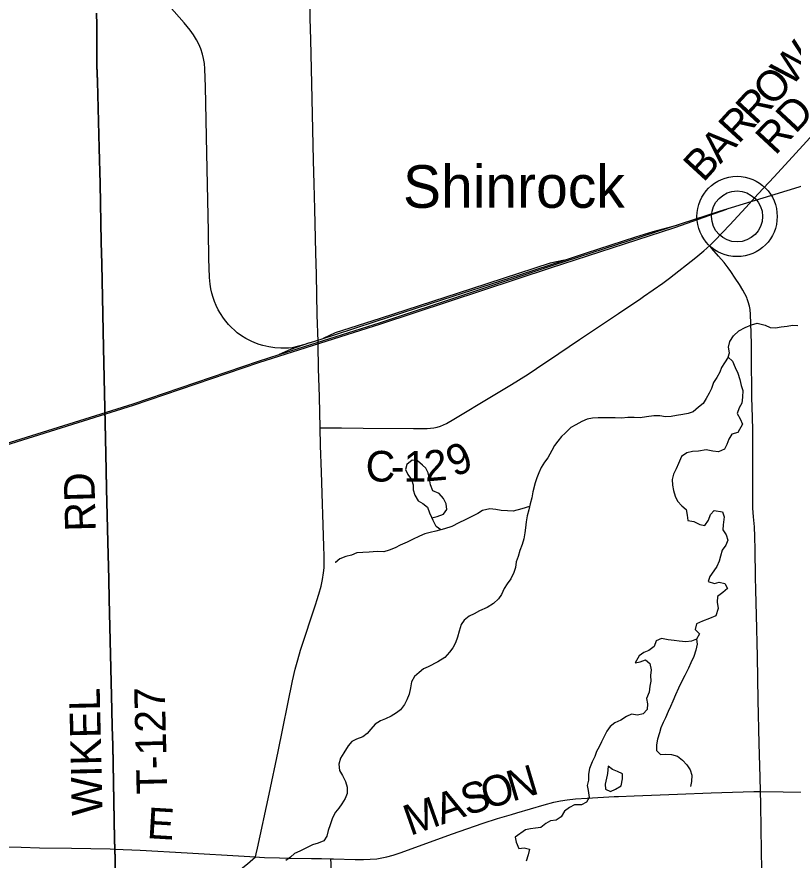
# Model space of a CAD drawing. Extents: x 0 to 34, y 0 to 22.
# Drawn here: x 4.241 to 5.679, y 14.854 to 16.417 of the extents above; entities that cross this region are included whole.
import ezdxf

# ---------------------------------------------------------------- set-up
doc = ezdxf.new("R2010")
doc.units = 0
for name, color, linetype in [('GM_X_Corporation', 7, 'Continuous'), ('GM_X_County_Road', 7, 'Continuous'), ('GM_X_County_Road_Text', 7, 'Continuous'), ('GM_X_Minor_Lake', 7, 'Continuous'), ('GM_X_Minor_River', 7, 'Continuous'), ('GM_X_Rail_Line', 7, 'Continuous'), ('GM_X_Township_Road', 7, 'Continuous'), ('GM_X_Township_Road_Text', 7, 'Continuous'), ('GM_X_Unincorporated', 7, 'Continuous'), ('GM_X_Unincorporated_Location', 7, 'Continuous'), ('GM_X_Unincorporated_Text', 7, 'Continuous')]:
    doc.layers.add(name, color=color, linetype=linetype)

msp = doc.modelspace()

# ---------------------------------------------------------------- linework, layer by layer
at = {"layer": 'GM_X_Corporation'}
for points in [[(4.4253, 14.7443), (4.4234, 14.8562), (4.4229, 14.8756), (4.4224, 14.8934), (4.4205, 14.999), (4.4193, 15.0674), (4.4183, 15.1016), (4.4175, 15.1326), (4.4124, 15.3377), (4.4117, 15.375), (4.4102, 15.4434), (4.4076, 15.5428), (4.4069, 15.5769), (4.4055, 15.636), (4.4042, 15.6919), (4.4017, 15.8037), (4.4009, 15.8658), (4.3987, 15.959), (4.3979, 15.9994), (4.3958, 16.1082), (4.3941, 16.1734), (4.3922, 16.2479), (4.3907, 16.2969), (4.3897, 16.3272), (4.3896, 16.3394), (4.3897, 16.3676), (4.3898, 16.4019), (4.3892, 16.4237)], [(4.3892, 16.4237), (4.3898, 16.4019), (4.3897, 16.3676), (4.3896, 16.3394), (4.3897, 16.3272), (4.3907, 16.2969), (4.3922, 16.2479), (4.3941, 16.1734), (4.3958, 16.1082), (4.3979, 15.9994), (4.3987, 15.959), (4.4009, 15.8658), (4.4017, 15.8037), (4.4042, 15.6919), (4.4055, 15.636), (4.4069, 15.5769), (4.4076, 15.5428), (4.4102, 15.4434), (4.4117, 15.375), (4.4124, 15.3377), (4.4175, 15.1326), (4.4183, 15.1016), (4.4193, 15.0674), (4.4205, 14.999), (4.4224, 14.8934), (4.4229, 14.8756), (4.4234, 14.8562), (4.4253, 14.7443)]]:
    msp.add_lwpolyline(points, dxfattribs=at)
at = {"layer": 'GM_X_County_Road'}
msp.add_line((5.6068, 14.9813), (5.6189, 14.9816), dxfattribs=at)
for points in [[(4.7995, 15.8093), (4.7993, 15.8152), (4.7978, 15.8649), (4.7962, 15.9395), (4.7952, 15.9798), (4.7933, 16.0606), (4.7922, 16.1072), (4.7911, 16.1507), (4.7878, 16.2936), (4.7859, 16.3743), (4.7848, 16.4147), (4.7839, 16.4582), (4.7817, 16.598), (4.7801, 16.7005), (4.7794, 16.7502), (4.7778, 16.8372), (4.7764, 16.8513)], [(5.5248, 15.9929), (5.5342, 16.0022), (5.5619, 16.0317), (5.5916, 16.0636), (5.6144, 16.089), (5.6443, 16.1207), (5.6844, 16.164), (5.7705, 16.2581), (5.8083, 16.2993), (5.8207, 16.3133), (5.8305, 16.3254), (5.8415, 16.3406), (5.871, 16.3844), (5.8764, 16.3924)], [(4.8034, 15.6551), (4.8115, 15.6552), (4.8178, 15.6553), (4.8426, 15.6552), (4.8831, 15.655), (4.9764, 15.6541), (5.0013, 15.6542), (5.0075, 15.6545), (5.0138, 15.6554), (5.0199, 15.6567), (5.026, 15.6585), (5.0318, 15.6609), (5.0374, 15.6636), (5.051, 15.6713), (5.0723, 15.6843), (5.0989, 15.7003), (5.1575, 15.7358), (5.1888, 15.755), (5.2042, 15.7653), (5.2453, 15.793), (5.2836, 15.8191), (5.356, 15.8675), (5.3973, 15.895), (5.4022, 15.8986), (5.4378, 15.9235), (5.4503, 15.9328), (5.4994, 15.9711), (5.5138, 15.983), (5.5248, 15.9929)], [(4.8034, 15.6551), (4.802, 15.7128), (4.8005, 15.7656), (4.7995, 15.8093)], [(4.6835, 14.8602), (4.6848, 14.8662), (4.6872, 14.8765), (4.7088, 14.9767), (4.7253, 15.0558), (4.7521, 15.1867), (4.757, 15.2079), (4.7618, 15.2258), (4.7671, 15.2437), (4.7952, 15.3292), (4.7973, 15.3357), (4.8008, 15.3471), (4.8049, 15.3621), (4.8075, 15.3743), (4.8095, 15.3866), (4.8105, 15.3959), (4.8108, 15.4022), (4.8108, 15.4177), (4.8103, 15.4364), (4.8059, 15.573), (4.8042, 15.6227), (4.8034, 15.6551)], [(5.158, 14.9391), (5.1676, 14.9419), (5.2183, 14.9568), (5.2363, 14.9615), (5.2486, 14.9641), (5.2609, 14.9661), (5.2763, 14.9678), (5.2981, 14.9693), (5.3476, 14.972), (5.3557, 14.9724)], [(5.3557, 14.9724), (5.3849, 14.9737), (5.4655, 14.9769), (5.5276, 14.9791), (5.5866, 14.981), (5.6068, 14.9813)], [(5.6189, 14.9816), (5.6612, 14.9812), (5.7761, 14.9788), (5.8879, 14.9768), (5.95, 14.9768), (6.0432, 14.9781), (6.2079, 14.9826)], [(4.8233, 14.857), (4.8277, 14.8569), (4.8681, 14.8555), (4.8836, 14.8555), (4.8959, 14.8559), (4.9083, 14.857), (4.9174, 14.8584), (4.9265, 14.8604), (4.9384, 14.8637), (4.9531, 14.8686), (5.0465, 14.9025), (5.1053, 14.9228), (5.1319, 14.9313), (5.158, 14.9391)], [(4.2151, 14.8788), (4.2494, 14.8781), (4.2835, 14.8772), (4.3426, 14.8764), (4.4141, 14.8755), (4.4231, 14.875)], [(4.4231, 14.875), (4.47, 14.8727), (4.557, 14.8679), (4.6626, 14.8616), (4.6835, 14.8602)], [(4.4272, 14.6629), (4.4314, 14.6655), (4.437, 14.6682), (4.4477, 14.6746), (4.4606, 14.6831), (4.4732, 14.6921), (4.4904, 14.7053), (4.5217, 14.7306), (4.5629, 14.7632), (4.6233, 14.8111), (4.6689, 14.8478), (4.6835, 14.8602)], [(4.6835, 14.8602), (4.6912, 14.8597), (4.7004, 14.8591), (4.7277, 14.8586), (4.7439, 14.8583), (4.7874, 14.8576), (4.8055, 14.8573), (4.8233, 14.857)]]:
    msp.add_lwpolyline(points, dxfattribs=at)
at = {"layer": 'GM_X_Minor_Lake'}
for points in [[(4.9931, 15.5861), (4.9834, 15.5943), (4.9739, 15.5954), (4.9641, 15.5874)], [(4.9641, 15.5874), (4.9611, 15.5782), (4.9654, 15.5691), (4.9727, 15.5596), (4.9754, 15.5498), (4.9755, 15.5403), (4.9786, 15.5304), (4.9847, 15.5202), (4.9935, 15.5149), (5.0019, 15.5085), (5.0058, 15.4979), (5.01, 15.4884), (5.0199, 15.4911), (5.032, 15.4954), (5.038, 15.5042), (5.0368, 15.5148), (5.0318, 15.5247), (5.0238, 15.5337), (5.0119, 15.5386), (5.0077, 15.5496), (5.0057, 15.5606), (5.0034, 15.572), (4.9991, 15.5807), (4.9931, 15.5861)], [(5.335, 15.0117), (5.3314, 14.9951), (5.3319, 14.9856), (5.341, 14.9818), (5.3505, 14.9857), (5.3611, 14.9922), (5.3633, 15.0048), (5.3632, 15.0143), (5.354, 15.0188), (5.3445, 15.0221), (5.3369, 15.0285)], [(5.3369, 15.0285), (5.3354, 15.0149), (5.335, 15.0117)]]:
    msp.add_lwpolyline(points, dxfattribs=at)
at = {"layer": 'GM_X_Minor_River'}
for points in [[(5.5592, 15.7861), (5.5614, 15.7945), (5.5598, 15.8048), (5.562, 15.8151), (5.5692, 15.8258), (5.5786, 15.8353), (5.5903, 15.8415), (5.6021, 15.8461), (5.6127, 15.8492), (5.6275, 15.8455), (5.6371, 15.8414), (5.647, 15.8407), (5.6572, 15.8423), (5.6686, 15.8439), (5.6781, 15.8455), (5.6883, 15.8448)], [(5.5592, 15.7861), (5.5521, 15.7755), (5.5468, 15.7674), (5.5434, 15.7583), (5.5382, 15.7488), (5.5322, 15.7392), (5.5281, 15.7282), (5.5236, 15.7194), (5.5183, 15.7095), (5.5127, 15.7007), (5.5044, 15.6938), (5.4942, 15.685), (5.4851, 15.6819), (5.4748, 15.6799), (5.4634, 15.6779), (5.4532, 15.6764), (5.4429, 15.6759), (5.4323, 15.6778), (5.4213, 15.6773), (5.4076, 15.6757), (5.3959, 15.6737), (5.3848, 15.6744), (5.3731, 15.6747), (5.3617, 15.6735), (5.3495, 15.6738), (5.3385, 15.6737), (5.3282, 15.6741), (5.3184, 15.674), (5.3077, 15.6732), (5.2979, 15.6712), (5.288, 15.667), (5.277, 15.6612), (5.2676, 15.6558), (5.2574, 15.6455), (5.2502, 15.639), (5.2438, 15.6306), (5.2374, 15.6225), (5.2325, 15.6134), (5.225, 15.6), (5.219, 15.592), (5.2126, 15.5821), (5.2081, 15.5718), (5.2044, 15.5626), (5.2014, 15.5535), (5.1974, 15.5367), (5.1951, 15.5257), (5.1926, 15.5143), (5.1896, 15.5032), (5.187, 15.4922), (5.1848, 15.4811), (5.1838, 15.4701), (5.1827, 15.4606), (5.1805, 15.4496), (5.1775, 15.4389), (5.173, 15.4278), (5.1701, 15.4172), (5.1663, 15.4073), (5.1649, 15.3966), (5.1619, 15.3871), (5.1563, 15.3753), (5.1495, 15.3665), (5.1439, 15.3577), (5.139, 15.3463), (5.1338, 15.3383), (5.1243, 15.3298), (5.1126, 15.3222), (5.0986, 15.316), (5.0884, 15.3106), (5.0793, 15.3067), (5.0702, 15.2991), (5.0646, 15.2911), (5.0609, 15.2789), (5.0575, 15.2678), (5.0542, 15.2568), (5.0493, 15.2476), (5.0429, 15.2396), (5.0342, 15.23), (5.021, 15.2216), (5.0036, 15.2127), (4.9949, 15.2089), (4.9865, 15.202), (4.9782, 15.1947), (4.9726, 15.1848), (4.9708, 15.1737), (4.9682, 15.1616), (4.9641, 15.1513), (4.9596, 15.1429), (4.9521, 15.133), (4.9445, 15.1272), (4.9351, 15.1214), (4.9241, 15.1164), (4.915, 15.1126), (4.9051, 15.1064), (4.8969, 15.0972), (4.8901, 15.0888), (4.8821, 15.0831), (4.8708, 15.0788), (4.8621, 15.0742), (4.8549, 15.0662), (4.8474, 15.0532), (4.841, 15.0433)], [(5.5592, 15.7861), (5.5668, 15.7786), (5.5719, 15.7672), (5.5769, 15.7566), (5.5804, 15.7452), (5.5831, 15.7338), (5.5862, 15.7247), (5.5855, 15.7122), (5.5841, 15.7011), (5.5792, 15.6924), (5.5759, 15.6817), (5.5816, 15.6722), (5.5855, 15.6624), (5.5769, 15.6467), (5.5659, 15.6436), (5.5602, 15.6345), (5.5569, 15.6246), (5.552, 15.6158), (5.5414, 15.6108), (5.5308, 15.6122), (5.5182, 15.6144), (5.5042, 15.6124), (5.4928, 15.6116), (5.4822, 15.6093), (5.4727, 15.6023), (5.4671, 15.5894), (5.4626, 15.5791), (5.4577, 15.5696), (5.4552, 15.5597), (5.456, 15.5494), (5.4576, 15.5395), (5.4611, 15.5289), (5.4653, 15.5194), (5.4733, 15.5107), (5.481, 15.5039), (5.4833, 15.4933), (5.4845, 15.4838), (5.4956, 15.482), (5.5063, 15.4763), (5.5161, 15.4745), (5.5229, 15.484), (5.5266, 15.4947), (5.5334, 15.502), (5.5483, 15.4998), (5.5517, 15.4907), (5.5499, 15.4759), (5.5489, 15.4663), (5.5554, 15.4569), (5.5585, 15.447), (5.5548, 15.4379), (5.548, 15.4287), (5.5447, 15.4176), (5.5424, 15.4081), (5.5379, 15.3982), (5.5327, 15.3902), (5.5252, 15.3799), (5.5222, 15.3707), (5.5336, 15.367), (5.5427, 15.3697), (5.5526, 15.3668), (5.558, 15.3577), (5.5493, 15.35), (5.5391, 15.3427), (5.5388, 15.3321), (5.5404, 15.3207), (5.5363, 15.307), (5.5242, 15.3019), (5.5113, 15.2973), (5.5003, 15.2923), (5.4977, 15.282), (5.5061, 15.2737), (5.5001, 15.2638), (5.491, 15.2603), (5.4808, 15.2587), (5.4686, 15.2601), (5.4591, 15.2616), (5.4477, 15.2627), (5.4355, 15.2649), (5.4257, 15.2606), (5.422, 15.2504), (5.4121, 15.2427), (5.403, 15.2392), (5.3943, 15.2327), (5.3868, 15.2197), (5.3963, 15.2221), (5.4062, 15.2252), (5.4142, 15.2187), (5.4162, 15.207), (5.4155, 15.1963), (5.4156, 15.1861), (5.4137, 15.1765), (5.4127, 15.1655), (5.4078, 15.1537), (5.4098, 15.1438), (5.4091, 15.1336), (5.4015, 15.1255), (5.3913, 15.1232), (5.3803, 15.1246), (5.3708, 15.1204), (5.3602, 15.1135), (5.3492, 15.1088)], [(5.1913, 15.5094), (5.1771, 15.5051), (5.1607, 15.5011), (5.1501, 15.5018), (5.1383, 15.5021), (5.1288, 15.504), (5.1174, 15.5054), (5.1041, 15.5019), (5.0954, 15.4966), (5.0841, 15.4912), (5.072, 15.4846), (5.0602, 15.4792), (5.0474, 15.4727), (5.0333, 15.4684), (5.0178, 15.4637), (5.0068, 15.4614), (4.9973, 15.4587), (4.9875, 15.4548), (4.9746, 15.4483), (4.9644, 15.4436), (4.9515, 15.4379), (4.9424, 15.4332), (4.931, 15.4286), (4.9212, 15.4259), (4.909, 15.4262), (4.8938, 15.4249), (4.8821, 15.4241), (4.871, 15.4237), (4.8612, 15.4194), (4.8506, 15.4167), (4.84, 15.4124), (4.8317, 15.4059), (4.8317, 15.4055)], [(5.0271, 15.4666), (5.0181, 15.4725), (5.01, 15.4884), (5.0123, 15.4842)], [(5.5001, 15.2638), (5.5017, 15.2543), (5.4991, 15.2436), (5.4954, 15.2314), (5.4902, 15.22), (5.4857, 15.2101), (5.4789, 15.1963), (5.4718, 15.1838), (5.4669, 15.1731), (5.4613, 15.1605), (5.4565, 15.1487), (5.452, 15.1391), (5.4479, 15.13), (5.443, 15.1182), (5.4389, 15.1094), (5.4344, 15.0995), (5.4318, 15.0904), (5.4281, 15.0782), (5.4263, 15.0679), (5.4263, 15.0572), (5.434, 15.0501), (5.4435, 15.0505), (5.4541, 15.0502), (5.4652, 15.0468), (5.4747, 15.0397), (5.4827, 15.031), (5.4885, 15.0219), (5.4916, 15.012), (5.4909, 14.9999), (5.4891, 14.9907)], [(5.3492, 15.1088), (5.3402, 15.1019), (5.3345, 15.0935), (5.3293, 15.0832), (5.3244, 15.0737), (5.3199, 15.0646), (5.3154, 15.0558), (5.3121, 15.0466), (5.3072, 15.0367), (5.3023, 15.0241), (5.3001, 15.0139), (5.3006, 15.0025), (5.298, 14.9926), (5.3, 14.9831), (5.3016, 14.9705), (5.2967, 14.9618), (5.2872, 14.9568), (5.2747, 14.9571), (5.2652, 14.9521), (5.2562, 14.9448), (5.2498, 14.9345), (5.2403, 14.9287), (5.2297, 14.9275), (5.2214, 14.9225), (5.2119, 14.9148), (5.2024, 14.9136), (5.1929, 14.9124), (5.1835, 14.9105), (5.1645, 14.8971), (5.1661, 14.8876), (5.1715, 14.8758), (5.1814, 14.8774), (5.1909, 14.8744), (5.1887, 14.8641), (5.185, 14.8523)], [(4.841, 15.0433), (4.838, 15.0319), (4.8393, 15.0205), (4.8446, 15.011), (4.85, 15), (4.8535, 14.9898), (4.8536, 14.978), (4.8495, 14.9684), (4.8435, 14.9585), (4.8378, 14.9505), (4.8314, 14.9432), (4.8262, 14.9329), (4.8217, 14.9196), (4.8184, 14.9093), (4.8158, 14.899), (4.8098, 14.8903), (4.7995, 14.886), (4.7889, 14.8829), (4.7802, 14.8787), (4.7655, 14.871), (4.7556, 14.8667), (4.7484, 14.8598), (4.7394, 14.8537)]]:
    msp.add_lwpolyline(points, dxfattribs=at)
at = {"layer": 'GM_X_Rail_Line'}
msp.add_line((4.7833, 15.8126), (4.8087, 15.8209), dxfattribs=at)
for points in [[(4.7274, 15.7912), (4.9149, 15.8505), (5.235, 15.9568), (5.5432, 16.0566), (5.6906, 16.1019), (6.056, 16.2214), (6.3367, 16.3138), (6.6888, 16.4288), (7.0003, 16.5302), (7.5012, 16.6931), (7.6844, 16.7528), (7.8339, 16.8018), (7.9505, 16.8406), (8.0234, 16.8694), (8.0878, 16.9029), (8.1469, 16.9344), (8.2358, 16.9935), (8.3923, 17.1058), (8.5744, 17.2368), (8.7463, 17.3593), (8.8719, 17.4493), (8.9, 17.4694)], [(4.7833, 15.8126), (4.7746, 15.8098), (4.7517, 15.8038), (4.7448, 15.8032), (4.7306, 15.8027), (4.7195, 15.8034), (4.7079, 15.8052), (4.697, 15.8077), (4.6901, 15.81), (4.682, 15.813), (4.6752, 15.8159), (4.6658, 15.8209), (4.6578, 15.8259), (4.6498, 15.8316), (4.6443, 15.8363), (4.6388, 15.8414), (4.6336, 15.8466), (4.6286, 15.8528), (4.6244, 15.8583), (4.6187, 15.8669), (4.6145, 15.8742), (4.6107, 15.8819), (4.6073, 15.8897), (4.6049, 15.8966), (4.6026, 15.9048), (4.6007, 15.9128), (4.5994, 15.9213), (4.5981, 15.9338), (4.5972, 15.9691), (4.5964, 16.0194), (4.5934, 16.164), (4.5909, 16.287), (4.5899, 16.3203), (4.5888, 16.3303), (4.5872, 16.3394), (4.5853, 16.3475), (4.5821, 16.3575), (4.5785, 16.3661), (4.5744, 16.3741), (4.5689, 16.3833), (4.5624, 16.3923), (4.5512, 16.4059), (4.4256, 16.5489)], [(3.2088, 15.2971), (3.2684, 15.3142), (3.4536, 15.3739), (3.5291, 15.3985), (3.8359, 15.4986), (4.0815, 15.5782), (4.2209, 15.6235), (4.4575, 15.6975), (4.6896, 15.7766), (4.9157, 15.8481), (5.2297, 15.9517), (5.4604, 16.0265), (5.5567, 16.0607)], [(5.2559, 15.9661), (5.2969, 15.9794), (5.388, 16.009), (5.4204, 16.019), (5.4663, 16.0317)], [(4.8087, 15.8209), (4.8298, 15.8277), (4.9054, 15.8524), (5.0308, 15.8931), (5.1746, 15.9397), (5.2559, 15.9661)], [(5.2559, 15.9661), (5.2293, 15.9605), (5.0838, 15.9132), (4.9147, 15.8581), (4.8312, 15.8312), (4.8087, 15.8209)], [(4.7833, 15.8126), (4.7484, 15.8008), (4.7274, 15.7912)], [(4.2201, 15.6258), (4.4567, 15.6999), (4.6888, 15.779), (4.7274, 15.7912)]]:
    msp.add_lwpolyline(points, dxfattribs=at)
at = {"layer": 'GM_X_Township_Road'}
for points in [[(4.4043, 15.6973), (4.4019, 15.8031), (4.4011, 15.8653), (4.3989, 15.9585), (4.3981, 15.9989), (4.396, 16.1076), (4.3943, 16.1728), (4.3924, 16.2473), (4.391, 16.2964), (4.3899, 16.3266), (4.3898, 16.3389), (4.3899, 16.3671), (4.3901, 16.4013), (4.3894, 16.4231)], [(5.6189, 14.9816), (5.6183, 15.0081), (5.6167, 15.0703), (5.6149, 15.151), (5.6132, 15.2318), (5.6114, 15.3082), (5.6104, 15.3547), (5.6098, 15.3795), (5.6089, 15.4293), (5.6082, 15.454), (5.6077, 15.4718), (5.6061, 15.4902), (5.6049, 15.5064), (5.6046, 15.5294), (5.6048, 15.659), (5.6044, 15.6673), (5.604, 15.6793), (5.6037, 15.689), (5.6035, 15.6986), (5.6032, 15.7065), (5.6031, 15.7123), (5.603, 15.7163), (5.6026, 15.733), (5.6025, 15.7688), (5.6022, 15.8098), (5.6017, 15.8312), (5.6004, 15.8652), (5.5996, 15.8745), (5.5986, 15.8805), (5.5964, 15.8891), (5.5945, 15.8944), (5.5934, 15.897), (5.5861, 15.9102), (5.5798, 15.9208), (5.572, 15.9329), (5.564, 15.9448), (5.559, 15.9521), (5.5515, 15.9618), (5.5414, 15.9736), (5.5291, 15.9876), (5.5248, 15.9929)], [(4.4231, 14.875), (4.4226, 14.8928), (4.4207, 14.9985), (4.4195, 15.0669), (4.4185, 15.101), (4.4177, 15.1321), (4.4126, 15.3372), (4.4119, 15.3744), (4.4104, 15.4428), (4.4078, 15.5422), (4.4071, 15.5764), (4.4057, 15.6354), (4.4044, 15.6913), (4.4043, 15.6973)], [(5.623, 14.7648), (5.6223, 14.7968), (5.6202, 14.9118), (5.6194, 14.9584), (5.6189, 14.9816)], [(4.4272, 14.6629), (4.4255, 14.7437), (4.4236, 14.8556), (4.4231, 14.875)], [(4.8339, 14.2956), (4.8334, 14.3442), (4.8329, 14.3908), (4.8324, 14.4592), (4.8316, 14.4965), (4.8288, 14.6249), (4.8286, 14.6382), (4.8273, 14.6954), (4.825, 14.7469), (4.8238, 14.8477), (4.8233, 14.857)]]:
    msp.add_lwpolyline(points, dxfattribs=at)
at = {"layer": 'GM_X_Unincorporated'}
for radius in [0.0744, 0.0472]:
    msp.add_circle((5.5755, 16.047), radius, dxfattribs=at)
at = {"layer": 'GM_X_Unincorporated_Location'}
msp.add_line((5.5755, 16.047), (5.5755, 16.047), dxfattribs=at)

# ---------------------------------------------------------------- texts
at = {"layer": 'GM_X_County_Road_Text'}
for s, height, rotation, p in [('W', 0.0568, 47.4644, (5.6752, 16.2856)), ('O', 0.0568, 47.4658, (5.6414, 16.2487)), ('R', 0.0568, 47.4665, (5.6099, 16.2143)), ('RD', 0.05682, 47.0941, (5.6464, 16.1586)), ('R', 0.0568, 47.4637, (5.5783, 16.18)), ('A', 0.0568, 47.4646, (5.5445, 16.1431)), ('B', 0.0568, 47.4667, (5.513, 16.1087)), ('9', 0.0568, 22.9924, (5.052, 15.5635)), ('C', 0.0568, 359.6078, (4.8874, 15.556)), ('1', 0.0568, 0.0579, (4.9579, 15.5555)), ('2', 0.0568, 4.9508, (4.9982, 15.5558)), ('-', 0.0568, 359.6944, (4.9342, 15.5557)), ('N', 0.0568, 16.6267, (5.1589, 14.9626)), ('S', 0.0568, 18.3365, (5.0751, 14.9361)), ('O', 0.0568, 17.0087, (5.1112, 14.948)), ('M', 0.0568, 19.4404, (4.9701, 14.8991)), ('A', 0.0568, 19.3093, (5.0282, 14.9196)), ('E', 0.0568, 356.6332, (4.4813, 14.8953))]:
    msp.add_text(s, height=height, rotation=rotation, dxfattribs=at).set_placement(p)
at = {"layer": 'GM_X_Township_Road_Text'}
for s, rotation, p in [('RD', 91.4755, (4.3877, 15.4639)), ('WIKEL', 91.2778, (4.4002, 14.9374)), ('T-127', 91.4049, (4.5203, 14.9773))]:
    msp.add_text(s, height=0.05682, rotation=rotation, dxfattribs=at).set_placement(p)
at = {"layer": 'GM_X_Unincorporated_Text'}
msp.add_text('Shinrock', height=0.07898, rotation=0, dxfattribs=at).set_placement((4.9567, 16.063))

doc.saveas('drawing.dxf')
